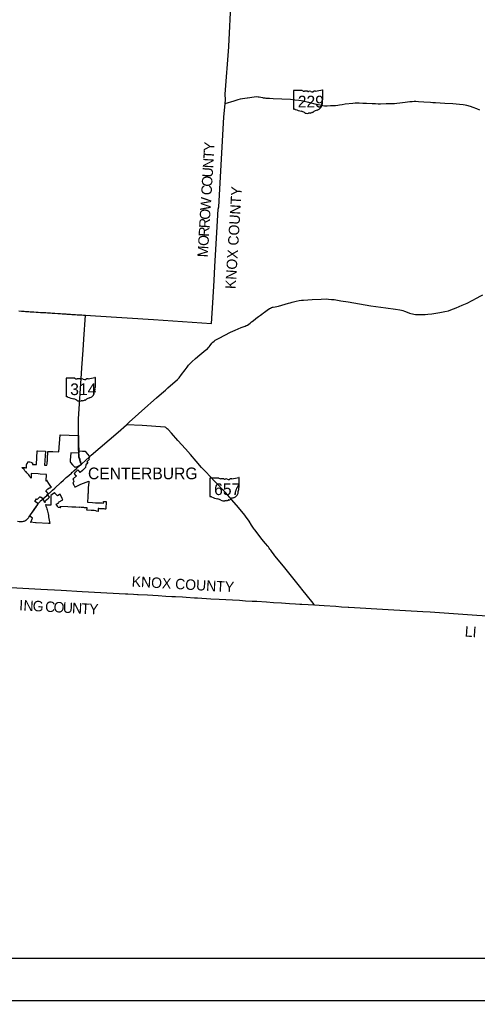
# Model space of a CAD drawing. Extents: x 1851937 to 2123937, y 78841 to 965467.
# Drawn here: x 1909296 to 1953112, y 789467 to 883220 of the extents above; entities that cross this region are included whole.
import ezdxf

# ---------------------------------------------------------------- set-up
doc = ezdxf.new("R2010")
doc.units = 0
for name, color, linetype in [('GM_X_Corporation', 7, 'Continuous'), ('GM_X_Corporation_Text', 7, 'Continuous'), ('GM_X_County', 7, 'Continuous'), ('GM_X_County_Text', 7, 'Continuous'), ('GM_X_State_Location', 7, 'Continuous'), ('GM_X_State_Route', 7, 'Continuous'), ('GM_X_State_Shield', 7, 'Continuous'), ('GM_X_US_Location', 7, 'Continuous'), ('GM_X_US_Route', 7, 'Continuous'), ('SH_Border', 7, 'Continuous'), ('SH_Cut_Line', 7, 'Continuous')]:
    doc.layers.add(name, color=color, linetype=linetype)

msp = doc.modelspace()

# ---------------------------------------------------------------- linework, layer by layer
at = {"layer": 'GM_X_Corporation'}
msp.add_lwpolyline([(1914951, 841986), (1914953, 841784), (1914954, 841776), (1914917, 841779), (1914202, 841823), (1914152, 841092), (1914142, 840939), (1914176, 840882), (1914362, 840675), (1914601, 840409), (1914651, 840452), (1914664, 840462), (1914665, 840463), (1914676, 840463), (1914689, 840463), (1914700, 840463), (1914710, 840463), (1914719, 840464), (1914728, 840464), (1914736, 840465), (1914743, 840467), (1914752, 840469), (1914760, 840471), (1914770, 840474), (1914778, 840477), (1914786, 840479), (1914793, 840482), (1914800, 840485), (1914807, 840488), (1914814, 840491), (1914821, 840494), (1914828, 840496), (1914836, 840497), (1914843, 840498), (1914852, 840500), (1914860, 840502), (1914867, 840504), (1914873, 840507), (1914879, 840509), (1914885, 840512), (1914891, 840515), (1914897, 840518), (1914903, 840521), (1914909, 840525), (1914915, 840530), (1914921, 840534), (1914928, 840539), (1914935, 840544), (1914941, 840548), (1914947, 840552), (1914953, 840555), (1914958, 840559), (1914962, 840562), (1914967, 840566), (1914972, 840570), (1914977, 840575), (1914983, 840580), (1914988, 840585), (1914992, 840590), (1914996, 840594), (1915000, 840598), (1915005, 840601), (1915013, 840607), (1915017, 840609), (1915021, 840612), (1915023, 840616), (1915027, 840620), (1915037, 840627), (1915045, 840631), (1915051, 840633), (1915059, 840633), (1915065, 840633), (1915068, 840633), (1915115, 840675), (1915160, 840716), (1915185, 840738), (1915209, 840760), (1915166, 840898), (1915150, 840948), (1915135, 840994), (1915078, 841176), (1915029, 841332), (1915009, 841396), (1914998, 841441), (1914991, 841478), (1914988, 841520), (1914985, 841602), (1914984, 841617), (1914977, 841775), (1914977, 841984), (1915331, 841967), (1915441, 841961), (1915573, 841981), (1915764, 841726), (1915976, 841444), (1915994, 841420), (1916012, 841396), (1915904, 841300), (1915991, 841191), (1915737, 840957), (1915837, 840814), (1915651, 840646), (1915606, 840395), (1915605, 840394), (1915584, 840375), (1915306, 840116), (1915109, 839931), (1915000, 840050), (1914882, 840178), (1914866, 840164), (1914814, 840118), (1914728, 840044), (1914708, 840025), (1914504, 839842), (1914591, 839745), (1914629, 839704), (1914728, 839594), (1914431, 839334), (1914414, 839319), (1914381, 839290), (1914460, 839185), (1914486, 839150), (1914460, 839126), (1914522, 839058), (1914396, 838950), (1914413, 838914), (1914438, 838857), (1914466, 838796), (1914493, 838736), (1914498, 838725), (1914520, 838676), (1914547, 838616), (1914574, 838556), (1914587, 838526), (1914775, 838623), (1915169, 838827), (1915400, 838912), (1915915, 839102), (1915875, 838607), (1915871, 838557), (1915868, 838507), (1915864, 838403), (1915859, 838303), (1915853, 838163), (1915849, 838063), (1915845, 837963), (1915843, 837938), (1915839, 837863), (1915832, 837763), (1915826, 837664), (1915819, 837564), (1915811, 837444), (1915799, 837256), (1915788, 837079), (1916262, 837054), (1916564, 837038), (1916699, 837031), (1916768, 837029), (1916786, 837028), (1917007, 837021), (1917163, 837017), (1917329, 837012), (1917339, 837164), (1917576, 837147), (1917535, 836462), (1917533, 836434), (1917533, 836432), (1917485, 836435), (1917383, 836442), (1917292, 836447), (1917127, 836459), (1916971, 836469), (1916871, 836475), (1916853, 836476), (1916831, 836477), (1916829, 836448), (1916817, 836208), (1916618, 836219), (1916621, 836279), (1916436, 836289), (1916152, 836306), (1915789, 836327), (1915744, 836329), (1915756, 836518), (1915758, 836548), (1915752, 836549), (1915613, 836558), (1915533, 836564), (1915508, 836566), (1915456, 836570), (1915403, 836573), (1915298, 836581), (1915194, 836588), (1915044, 836599), (1915048, 836587), (1915019, 836588), (1914669, 836608), (1914557, 836614), (1914504, 836617), (1914303, 836628), (1914291, 836628), (1913899, 836648), (1913157, 836686), (1913197, 836559), (1913008, 836577), (1912984, 836579), (1912926, 836697), (1912807, 836903), (1913047, 837039), (1913034, 837077), (1913429, 837312), (1913430, 837312), (1913366, 837448), (1913179, 837844), (1913071, 837788), (1912911, 837704), (1912849, 837772), (1912846, 837775), (1912758, 837872), (1912704, 837931), (1912630, 838012), (1912528, 837926), (1912296, 837729), (1912287, 836796), (1911938, 836816), (1911835, 836822), (1911795, 836824), (1911765, 836826), (1911815, 836708), (1911861, 836588), (1911902, 836467), (1911940, 836344), (1911974, 836221), (1912004, 836096), (1912029, 835971), (1912056, 835826), (1912059, 835697), (1912178, 835057), (1912070, 835062), (1912058, 835062), (1910885, 835116), (1910808, 835120), (1910351, 835165), (1910364, 835194), (1910533, 835569), (1910266, 835764), (1910412, 835962), (1910622, 836252), (1910751, 836449), (1910908, 836687), (1910959, 836766), (1910973, 836788), (1911028, 836873), (1911056, 836917), (1911082, 836955), (1911057, 836969), (1910913, 837051), (1910901, 837059), (1910751, 837144), (1910922, 837400), (1910966, 837353), (1911238, 837601), (1911253, 837608), (1911281, 837556), (1911363, 837580), (1911376, 837563), (1911488, 837416), (1911508, 837389), (1911514, 837394), (1911530, 837365), (1911572, 837292), (1911659, 837135), (1911704, 837055), (1911778, 837121), (1911735, 837203), (1911773, 837237), (1911908, 837357), (1912047, 837482), (1912163, 837584), (1911995, 837783), (1911973, 837808), (1912010, 837841), (1912031, 837860), (1912062, 837887), (1912063, 837888), (1912041, 837913), (1911793, 838188), (1911986, 838361), (1912169, 838449), (1912212, 838469), (1912341, 838531), (1912336, 838538), (1912330, 838546), (1912323, 838558), (1912293, 838602), (1912167, 838789), (1912109, 838876), (1911937, 839131), (1911900, 839186), (1911848, 839144), (1911823, 839124), (1911824, 839146), (1911868, 839737), (1911275, 839775), (1911072, 839788), (1910410, 839832), (1910390, 839375), (1910319, 839486), (1910243, 839595), (1910165, 839701), (1910082, 839804), (1909997, 839905), (1909925, 839983), (1909872, 840038), (1909811, 840103), (1909764, 840159), (1909723, 840208), (1909555, 840388), (1909535, 840409), (1909694, 840399), (1909734, 840397), (1909807, 840392), (1909891, 840387), (1909954, 840383), (1909955, 840403), (1909968, 840620), (1909979, 840791), (1910058, 840782), (1910069, 840950), (1910182, 840943), (1910263, 840938), (1910413, 840929), (1910410, 840875), (1910535, 840867), (1910525, 840708), (1910915, 840684), (1910991, 841994), (1910995, 841994), (1911763, 841956), (1911689, 840637), (1911903, 840625), (1911920, 840756), (1911937, 840755), (1911945, 840878), (1911946, 840938), (1911951, 841035), (1911957, 841134), (1911960, 841193), (1911967, 841324), (1911970, 841384), (1911975, 841479), (1911980, 841559), (1911984, 841639), (1911988, 841719), (1911996, 841856), (1912001, 841945), (1912201, 841935), (1912383, 841926), (1912482, 841921), (1913061, 841893), (1913166, 843522), (1914906, 843461), (1914936, 843460), (1914942, 842809), (1914942, 842763), (1914944, 842613)], close=True, dxfattribs=at)
at = {"layer": 'GM_X_County'}
for points in [[(1909228, 855373), (1909473, 855356), (1909636, 855344), (1909653, 855344), (1909718, 855340), (1909865, 855332), (1910013, 855322), (1910176, 855313), (1910323, 855301), (1910496, 855291), (1910667, 855279), (1910886, 855263), (1911089, 855250), (1911289, 855238), (1911595, 855220), (1911806, 855208), (1911952, 855199), (1912116, 855189), (1912255, 855180), (1912402, 855170), (1912532, 855160), (1912680, 855151), (1912942, 855134), (1913203, 855117), (1913367, 855107), (1913531, 855095), (1913629, 855089), (1913727, 855083), (1913825, 855078), (1913907, 855073), (1914005, 855066), (1914103, 855060), (1914169, 855055), (1914300, 855047), (1914479, 855035), (1914638, 855024), (1914807, 855015), (1914960, 855004), (1915150, 854993), (1915265, 854986), (1915428, 854976), (1915511, 854971), (1915616, 854967), (1916548, 854895), (1922109, 854540), (1924891, 854366), (1927657, 854187), (1927783, 856133), (1927916, 858268), (1927987, 859627), (1928187, 862864), (1928313, 865108), (1928357, 865313), (1928848, 873886), (1928976, 875213), (1928998, 875562), (1928986, 876108), (1929311, 880616), (1929312, 880640), (1929553, 885197)], [(1955665, 826095), (1953053, 826265), (1948592, 826572), (1947877, 826620), (1944569, 826800), (1940804, 827028), (1940744, 827034), (1940112, 827070), (1939560, 827107), (1938444, 827185), (1937968, 827208), (1937532, 827240), (1936924, 827276), (1936311, 827314), (1936120, 827325), (1935716, 827350), (1935132, 827380), (1934356, 827436), (1933609, 827479), (1932937, 827525), (1932012, 827584), (1931539, 827608), (1930920, 827644), (1930354, 827679), (1929657, 827724), (1928412, 827800), (1927588, 827835), (1926322, 827910), (1926021, 827928), (1925241, 827975), (1924884, 827998), (1924212, 828035), (1923869, 828056), (1923280, 828086), (1922550, 828131), (1921535, 828187), (1920653, 828242), (1920580, 828244), (1920206, 828267), (1919668, 828292), (1919433, 828302), (1915271, 828536), (1913287, 828636), (1911340, 828742), (1906703, 828996)]]:
    msp.add_lwpolyline(points, dxfattribs=at)
at = {"layer": 'GM_X_State_Route'}
for p, q in [((1932725, 855249), (1932868, 855355)), ((1932868, 855355), (1932978, 855435)), ((1948747, 855103), (1948926, 855129)), ((1931487, 854316), (1931655, 854442)), ((1931655, 854442), (1931920, 854638)), ((1931920, 854638), (1932176, 854833)), ((1919515, 844497), (1919781, 844733)), ((1915084, 840619), (1915206, 840729)), ((1913609, 839299), (1913760, 839445)), ((1913760, 839445), (1913993, 839645)), ((1910174, 835645), (1910264, 835774)), ((1933258, 832598), (1933182, 832706))]:
    msp.add_line(p, q, dxfattribs=at)
for points in [[(1928977, 875210), (1929841, 875464), (1930219, 875576), (1930441, 875633), (1930630, 875678), (1930842, 875720), (1931070, 875749)], [(1931070, 875749), (1931122, 875756), (1931751, 875834)], [(1931751, 875834), (1932013, 875856), (1932114, 875854), (1932219, 875840), (1932371, 875811), (1932530, 875774)], [(1932530, 875774), (1932623, 875753), (1932779, 875732), (1932861, 875721), (1933208, 875707), (1933557, 875691), (1934394, 875642), (1935233, 875604), (1935645, 875564), (1936007, 875517), (1936236, 875488), (1936400, 875455), (1936962, 875329), (1937690, 875148)], [(1937690, 875148), (1938051, 875075), (1938323, 875020), (1938467, 874992), (1938725, 874990), (1939067, 874996), (1939542, 875013), (1939747, 875037), (1939923, 875068), (1940160, 875110), (1940467, 875157), (1941178, 875245), (1941419, 875260)], [(1941419, 875260), (1941558, 875263), (1941792, 875256), (1942147, 875235), (1942502, 875219), (1943046, 875197), (1943347, 875189), (1943621, 875173), (1943833, 875177), (1944382, 875191), (1944926, 875214), (1945176, 875214), (1945391, 875231), (1945700, 875266), (1946200, 875325), (1946656, 875385), (1946869, 875398), (1947049, 875411), (1947228, 875409), (1947484, 875395), (1947996, 875362), (1948617, 875322), (1948835, 875311), (1948871, 875304), (1949099, 875295), (1949989, 875238), (1950772, 875196), (1951395, 875153), (1951753, 875112), (1951943, 875081), (1952060, 875053), (1952411, 874938), (1952672, 874856), (1953013, 874727), (1953327, 874607)], [(1953099, 856631), (1953363, 856770), (1953647, 856909)], [(1933509, 855720), (1933579, 855741), (1933755, 855780), (1934080, 855839), (1935041, 856101), (1935188, 856140)], [(1935188, 856140), (1935391, 856195), (1935766, 856292), (1936051, 856357), (1936263, 856386), (1936476, 856409), (1936868, 856428), (1937294, 856450), (1938156, 856495), (1938672, 856514)], [(1938672, 856514), (1938848, 856509), (1939133, 856478), (1939405, 856451), (1940034, 856352), (1940754, 856232), (1942385, 855940), (1942903, 855866)], [(1948926, 855129), (1949519, 855232), (1950001, 855322), (1950336, 855397), (1950569, 855472), (1951083, 855678), (1951641, 855914), (1952137, 856122), (1953099, 856631)], [(1932176, 854833), (1932343, 854958), (1932491, 855070)], [(1932491, 855070), (1932632, 855177), (1932725, 855249)], [(1932978, 855435), (1933199, 855598), (1933312, 855652)], [(1933312, 855652), (1933400, 855687), (1933430, 855697), (1933509, 855720)], [(1942903, 855866), (1944355, 855662), (1945268, 855542), (1945688, 855476), (1945839, 855445), (1945963, 855411), (1946123, 855365)], [(1946123, 855365), (1946385, 855264), (1946625, 855174), (1946733, 855134), (1946912, 855088)], [(1946912, 855088), (1947014, 855065), (1947175, 855046), (1947279, 855033), (1947529, 855033), (1947974, 855038), (1948114, 855045), (1948362, 855059), (1948747, 855103)], [(1914937, 843490), (1914940, 845074), (1915228, 849386), (1915265, 849923), (1915382, 851619), (1915455, 852677), (1915617, 854964)], [(1927438, 851934), (1927527, 852070), (1927693, 852290), (1927791, 852390), (1927914, 852493), (1928021, 852573), (1928145, 852643), (1928410, 852781), (1929472, 853332), (1929935, 853532), (1930513, 853784), (1930890, 853932), (1930979, 853969), (1931030, 853990), (1931102, 854026), (1931357, 854218), (1931487, 854316)], [(1925139, 849735), (1925324, 850008), (1925451, 850177), (1925565, 850299), (1925780, 850515), (1926122, 850820), (1926543, 851178), (1927135, 851645), (1927267, 851752), (1927378, 851865), (1927438, 851934)], [(1919781, 844733), (1921554, 846319), (1921848, 846578), (1922394, 847060), (1922886, 847495), (1923254, 847814), (1923469, 848015), (1924394, 848807), (1924478, 848878), (1924582, 848987), (1924795, 849292), (1925139, 849735)], [(1916064, 841501), (1916141, 841573), (1918723, 843786), (1919515, 844497)], [(1926772, 840333), (1926710, 840398), (1926209, 841017), (1925663, 841633), (1925175, 842187), (1924447, 843000), (1923822, 843688), (1923505, 844026), (1923417, 844114), (1923356, 844167), (1923277, 844232), (1923230, 844268), (1921013, 844405), (1919515, 844497)], [(1914937, 843438), (1914937, 843448), (1914937, 843490)], [(1914951, 841794), (1914948, 842220), (1914942, 842813), (1914937, 843438)], [(1915206, 840729), (1915167, 840799), (1915024, 841247), (1914975, 841393), (1914965, 841425), (1914954, 841508), (1914951, 841778), (1914951, 841794)], [(1915206, 840729), (1915631, 841108), (1915948, 841394)], [(1915948, 841394), (1915986, 841429), (1916064, 841501)], [(1913993, 839645), (1914248, 839863), (1914341, 839950), (1914360, 839968), (1914486, 840086), (1914746, 840313), (1915052, 840590), (1915084, 840619)], [(1933182, 832706), (1933107, 832817), (1933042, 832900), (1932826, 833153), (1932489, 833564), (1931926, 834279), (1931804, 834446), (1931759, 834504), (1931496, 834896), (1931260, 835284), (1931106, 835508), (1930990, 835664), (1930841, 835846), (1930258, 836581), (1929617, 837329), (1928988, 838007), (1927950, 839110), (1927124, 839996), (1927029, 840084), (1926772, 840333)], [(1912409, 838196), (1912456, 838238), (1912673, 838437), (1913244, 838979), (1913507, 839200), (1913609, 839299)], [(1912052, 837885), (1912172, 837986), (1912188, 837999), (1912409, 838196)], [(1911063, 836944), (1911113, 837012), (1911188, 837102), (1911249, 837161), (1911308, 837217), (1911348, 837255), (1911368, 837274), (1911387, 837291), (1911507, 837394)], [(1911507, 837394), (1911519, 837404), (1911896, 837745), (1911973, 837816)], [(1911973, 837816), (1912032, 837869), (1912052, 837885)], [(1910264, 835774), (1910621, 836286), (1910904, 836697), (1911001, 836848), (1911006, 836857), (1911048, 836922), (1911063, 836944)], [(1909580, 835242), (1909667, 835261), (1909741, 835288), (1909809, 835322), (1909888, 835364), (1909952, 835408), (1910015, 835468), (1910087, 835538), (1910138, 835593), (1910174, 835645)], [(1909086, 835267), (1909267, 835252), (1909580, 835242)], [(1936429, 828622), (1936084, 829051), (1934685, 830813), (1933918, 831748), (1933736, 831978), (1933598, 832159), (1933474, 832325), (1933340, 832491), (1933258, 832598)], [(1937533, 827237), (1937389, 827423), (1936715, 828266), (1936429, 828622)]]:
    msp.add_lwpolyline(points, dxfattribs=at)
at = {"layer": 'GM_X_State_Shield'}
for p, q in [((1935508, 876405), (1935508, 874704)), ((1936356, 876434), (1935536, 876434)), ((1938310, 875586), (1938310, 876476)), ((1938310, 875586), (1938310, 875586)), ((1913746, 848905), (1913746, 847204)), ((1914594, 848934), (1913774, 848934)), ((1916548, 848086), (1916548, 848976)), ((1916547, 848087), (1916548, 848086)), ((1927509, 839352), (1927509, 837651)), ((1928357, 839382), (1927537, 839382)), ((1930311, 838534), (1930311, 839424)), ((1930311, 838534), (1930311, 838534))]:
    msp.add_line(p, q, dxfattribs=at)
for centre, major_axis, start_param, end_param in [((1935540, 876408), (32.5, 0), 1.712693, 3.28349), ((1936552, 876632), (315, 0), 4.042523, 4.731795), ((1936656, 875479), (1130, 0), 1.404758, 1.657858), ((1936913, 876417), (90.8, 0), 3.836095, 5.185415), ((1937046, 876221), (189, 0), 0.950623, 2.079405), ((1937290, 876490), (227, 0), 4.081561, 5.145723), ((1937691, 875914), (598, 0), 1.699011, 2.107814), ((1937312, 878753), (2971, 0), 4.814394, 5.042369), ((1938279, 876480), (31.2, 0), 6.141152, 7.989035), ((1937478, 875101), (743, 0), 5.101752, 6.440018), ((1938422, 875214), (211, 0), 2.387724, 3.262537), ((1938303, 875521), (48.3, 0), 1.883978, 3.671073), ((1937996, 875408), (290, 0), 5.934695, 6.695948), ((1938277, 875583), (33.4, 0), 5.05454, 6.418171), ((1935541, 874700), (32.7, 0), 3.00124, 4.508301), ((1935546, 874874), (250, 0), 4.665946, 4.897461), ((1935597, 874605), (90.1, 0), 0.519207, 1.627899), ((1936734, 876134), (2146, 0), 4.195997, 4.488961), ((1936095, 873939), (671, 0), 0.823519, 1.323587), ((1936821, 874597), (426, 0), 4.026481, 4.996735), ((1937067, 874009), (350, 0), 1.495662, 1.94098), ((1937098, 874470), (227, 0), 4.691044, 5.507374), ((1937303, 874305), (63.9, 0), 1.147584, 2.315152), ((1937276, 874539), (240, 0), 4.937069, 5.64225), ((1937792, 874226), (407, 0), 1.647645, 2.488434), ((1913778, 848908), (32.5, 0), 1.712693, 3.28349), ((1914789, 849132), (315, 0), 4.042523, 4.731795), ((1914894, 847979), (1130, 0), 1.404758, 1.657858), ((1915150, 848917), (90.8, 0), 3.836095, 5.185415), ((1915284, 848721), (189, 0), 0.950623, 2.079405), ((1915527, 848990), (227, 0), 4.081561, 5.145723), ((1915929, 848414), (598, 0), 1.699011, 2.107814), ((1915550, 851253), (2971, 0), 4.814394, 5.042369), ((1916517, 848980), (31.2, 0), 6.141152, 7.989035), ((1915716, 847601), (743, 0), 5.101752, 6.440018), ((1916659, 847714), (211, 0), 2.387724, 3.262537), ((1916540, 848021), (48.3, 0), 1.883978, 3.671073), ((1916233, 847909), (290, 0), 5.934695, 6.695948), ((1916514, 848083), (33.4, 0), 5.05454, 6.418171), ((1913778, 847200), (32.7, 0), 3.00124, 4.508301), ((1913783, 847374), (250, 0), 4.665946, 4.897461), ((1913834, 847105), (90.1, 0), 0.519207, 1.627899), ((1914972, 848634), (2146, 0), 4.195997, 4.488961), ((1914332, 846439), (671, 0), 0.823519, 1.323587), ((1915058, 847097), (426, 0), 4.026481, 4.996735), ((1915305, 846509), (350, 0), 1.495662, 1.94098), ((1915336, 846970), (227, 0), 4.691044, 5.507374), ((1915541, 846805), (63.9, 0), 1.147584, 2.315152), ((1915514, 847039), (240, 0), 4.937069, 5.64225), ((1916029, 846726), (407, 0), 1.647645, 2.488434), ((1927541, 839356), (32.5, 0), 1.712693, 3.28349), ((1928553, 839579), (315, 0), 4.042523, 4.731795), ((1928657, 838427), (1130, 0), 1.404758, 1.657858), ((1928914, 839365), (90.8, 0), 3.836095, 5.185415), ((1929047, 839168), (189, 0), 0.950623, 2.079405), ((1929291, 839438), (227, 0), 4.081561, 5.145723), ((1929692, 838862), (598, 0), 1.699011, 2.107814), ((1929313, 841701), (2971, 0), 4.814394, 5.042369), ((1930280, 839428), (31.2, 0), 6.141152, 7.989035), ((1930423, 838162), (211, 0), 2.387724, 3.262537), ((1930304, 838469), (48.3, 0), 1.883978, 3.671073), ((1929997, 838356), (290, 0), 5.934695, 6.695948), ((1930278, 838531), (33.4, 0), 5.05454, 6.418171), ((1927542, 837648), (32.7, 0), 3.00124, 4.508301), ((1927546, 837822), (250, 0), 4.665946, 4.897461), ((1927598, 837553), (90.1, 0), 0.519207, 1.627899), ((1928735, 839082), (2146, 0), 4.195997, 4.488961), ((1928096, 836887), (671, 0), 0.823519, 1.323587), ((1928822, 837545), (426, 0), 4.026481, 4.996735), ((1929068, 836957), (350, 0), 1.495662, 1.94098), ((1929099, 837417), (227, 0), 4.691044, 5.507374), ((1929304, 837253), (63.9, 0), 1.147584, 2.315152), ((1929277, 837486), (240, 0), 4.937069, 5.64225), ((1929793, 837174), (407, 0), 1.647645, 2.488434), ((1929479, 838048), (743, 0), 5.101752, 6.440018)]:
    msp.add_ellipse(centre, major_axis=major_axis, ratio=0.8, start_param=start_param, end_param=end_param, dxfattribs=at)
at = {"layer": 'GM_X_US_Route'}
for p, q in [((1932725, 855249), (1932868, 855355)), ((1932868, 855355), (1932978, 855435)), ((1948747, 855103), (1948926, 855129)), ((1931487, 854316), (1931655, 854442)), ((1931655, 854442), (1931920, 854638)), ((1931920, 854638), (1932176, 854833)), ((1919515, 844497), (1919781, 844733)), ((1915084, 840619), (1915206, 840729)), ((1913609, 839299), (1913760, 839445)), ((1913760, 839445), (1913993, 839645)), ((1910174, 835645), (1910264, 835774))]:
    msp.add_line(p, q, dxfattribs=at)
for points in [[(1953099, 856631), (1953363, 856770), (1953647, 856909)], [(1933509, 855720), (1933579, 855741), (1933755, 855780), (1934080, 855839), (1935041, 856101), (1935188, 856140)], [(1935188, 856140), (1935391, 856195), (1935766, 856292), (1936051, 856357), (1936263, 856386), (1936476, 856409), (1936868, 856428), (1937294, 856450), (1938156, 856495), (1938672, 856514)], [(1938672, 856514), (1938848, 856509), (1939133, 856478), (1939405, 856451), (1940034, 856352), (1940754, 856232), (1942385, 855940), (1942903, 855866)], [(1948926, 855129), (1949519, 855232), (1950001, 855322), (1950336, 855397), (1950569, 855472), (1951083, 855678), (1951641, 855914), (1952137, 856122), (1953099, 856631)], [(1932176, 854833), (1932343, 854958), (1932491, 855070)], [(1932491, 855070), (1932632, 855177), (1932725, 855249)], [(1932978, 855435), (1933199, 855598), (1933312, 855652)], [(1933312, 855652), (1933400, 855687), (1933430, 855697), (1933509, 855720)], [(1942903, 855866), (1944355, 855662), (1945268, 855542), (1945688, 855476), (1945839, 855445), (1945963, 855411), (1946123, 855365)], [(1946123, 855365), (1946385, 855264), (1946625, 855174), (1946733, 855134), (1946912, 855088)], [(1946912, 855088), (1947014, 855065), (1947175, 855046), (1947279, 855033), (1947529, 855033), (1947974, 855038), (1948114, 855045), (1948362, 855059), (1948747, 855103)], [(1927438, 851934), (1927527, 852070), (1927693, 852290), (1927791, 852390), (1927914, 852493), (1928021, 852573), (1928145, 852643), (1928410, 852781), (1929472, 853332), (1929935, 853532), (1930513, 853784), (1930890, 853932), (1930979, 853969), (1931030, 853990), (1931102, 854026), (1931357, 854218), (1931487, 854316)], [(1925139, 849735), (1925324, 850008), (1925451, 850177), (1925565, 850299), (1925780, 850515), (1926122, 850820), (1926543, 851178), (1927135, 851645), (1927267, 851752), (1927378, 851865), (1927438, 851934)], [(1919781, 844733), (1921554, 846319), (1921848, 846578), (1922394, 847060), (1922886, 847495), (1923254, 847814), (1923469, 848015), (1924394, 848807), (1924478, 848878), (1924582, 848987), (1924795, 849292), (1925139, 849735)], [(1916064, 841501), (1916141, 841573), (1918723, 843786), (1919515, 844497)], [(1915206, 840729), (1915631, 841108), (1915948, 841394)], [(1915948, 841394), (1915986, 841429), (1916064, 841501)], [(1913993, 839645), (1914248, 839863), (1914341, 839950), (1914360, 839968), (1914486, 840086), (1914746, 840313), (1915052, 840590), (1915084, 840619)], [(1912409, 838196), (1912456, 838238), (1912673, 838437), (1913244, 838979), (1913507, 839200), (1913609, 839299)], [(1912052, 837885), (1912172, 837986), (1912188, 837999), (1912409, 838196)], [(1911063, 836944), (1911113, 837012), (1911188, 837102), (1911249, 837161), (1911308, 837217), (1911348, 837255), (1911368, 837274), (1911387, 837291), (1911507, 837394)], [(1911507, 837394), (1911519, 837404), (1911896, 837745), (1911973, 837816)], [(1911973, 837816), (1912032, 837869), (1912052, 837885)], [(1910264, 835774), (1910621, 836286), (1910904, 836697), (1911001, 836848), (1911006, 836857), (1911048, 836922), (1911063, 836944)], [(1909580, 835242), (1909667, 835261), (1909741, 835288), (1909809, 835322), (1909888, 835364), (1909952, 835408), (1910015, 835468), (1910087, 835538), (1910138, 835593), (1910174, 835645)], [(1909086, 835267), (1909267, 835252), (1909580, 835242)]]:
    msp.add_lwpolyline(points, dxfattribs=at)
at = {"layer": 'SH_Border'}
msp.add_lwpolyline([(1863937, 961467), (2119937, 961467), (2119937, 793467), (1863937, 793467)], close=True, dxfattribs=at)
at = {"layer": 'SH_Cut_Line'}
msp.add_lwpolyline([(1851937, 789467), (2123937, 789467), (2123937, 965467), (1851937, 965467)], close=True, dxfattribs=at)

# ---------------------------------------------------------------- texts
at = {"layer": 'GM_X_Corporation_Text'}
msp.add_text('CENTERBURG', height=1120, rotation=0.00001, dxfattribs=at).set_placement((1915842, 839281))
at = {"layer": 'GM_X_County_Text'}
for s, rotation, p in [('Y', 86.58895, (1927918, 870621)), ('T', 86.58706, (1927874, 869874)), ('N', 86.58902, (1927821, 868991)), ('O', 86.5871, (1927716, 867226)), ('U', 86.58833, (1927769, 868108)), ('C', 86.58334, (1927668, 866413)), ('KNOX COUNTY', 86.44803, (1929968, 857440)), ('W', 86.02006, (1927569, 864949)), ('O', 86.57375, (1927516, 864069)), ('R', 86.66054, (1927468, 863257)), ('O', 86.66435, (1927370, 861561)), ('R', 86.66508, (1927421, 862444)), ('M', 86.66387, (1927306, 860476)), ('KNOX COUNTY', 356.77031, (1920006, 829027)), ('I', 356.88612, (1909237, 826757)), ('N', 356.88946, (1909645, 826735)), ('G', 356.88852, (1910529, 826687)), ('C', 356.88774, (1911715, 826622)), ('O', 356.88848, (1912528, 826578)), ('U', 356.88852, (1913411, 826530)), ('N', 356.88834, (1914294, 826482)), ('T', 356.88841, (1915177, 826434)), ('Y', 356.88834, (1915924, 826394)), ('L', 356.12071, (1951879, 824250)), ('I', 356.12268, (1952625, 824199))]:
    msp.add_text(s, height=1000, rotation=rotation, dxfattribs=at).set_placement(p)
at = {"layer": 'GM_X_State_Location'}
for s, p in [('229', (1936538, 875134)), ('314', (1914775, 847634)), ('657', (1928538, 838082))]:
    msp.add_text(s, height=1, rotation=0.00001, dxfattribs=at).set_placement(p)
for s, p in [('s', (1936891, 875207)), ('r', (1936891, 875207)), ('s', (1915128, 847707)), ('r', (1915128, 847707)), ('s', (1928891, 838155)), ('r', (1928891, 838155))]:
    msp.add_text(s, height=1, dxfattribs=at).set_placement(p)
at = {"layer": 'GM_X_State_Shield'}
for s, p in [('229', (1935920, 874824)), ('314', (1914141, 847324)), ('657', (1927916, 837771))]:
    msp.add_text(s, height=1120.7, dxfattribs=at).set_placement(p)
at = {"layer": 'GM_X_US_Location'}
for s in ['0', '/']:
    msp.add_text(s, height=1, dxfattribs=at).set_placement((1925876, 850596))

doc.saveas('drawing.dxf')
